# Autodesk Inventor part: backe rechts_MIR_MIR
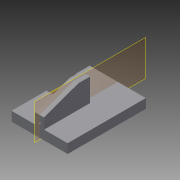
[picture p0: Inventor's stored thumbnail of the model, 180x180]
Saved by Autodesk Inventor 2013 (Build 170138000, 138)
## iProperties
Created: 2012-11
Part Number: backe rechts_MIR_MIR
Material: Allgemein
Document SubType Name: Modeling
Designer: otto
Density: 1 g/cm^3
Mass: 3948.56 g
Surface Area: 4189.4 cm^2
Volume: 3948.56 cm^3
d0: 1,000 oE
d1: 10,000 mm
d2: 10,000 mm
d3: 10,000 mm
d4: 60,000 mm
d5: 1,500 mm
d6: 0,00 grd
d7: 15,000 mm
d8: 0,00 grd
d9: 250,000 mm
d10: 49,000 mm
d11: 125,000 mm
d12: 0,00 grd
d13: 30,000 mm
d15: 200,000 mm
d16: 0,00 grd
d29: 5,000 mm
d31: 196,750 mm
d32: 0,00 grd
d33: 16,500 mm
d34: 0,00 grd
d35: 60,000 mm
d36: 0,00 grd
d37: 15,000 mm
d38: 0,00 grd
d0_1: 10,000 mm
Author: otto
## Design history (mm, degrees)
derived "backe rechts_MIR.ipt"
  sketch "Skizze2"
    geometry: L1 (62.842, 56.837)-(-16.083, -22.088) reference; L2 (62.842, 122.085)-(62.842, 56.837) reference; L3 (-3.226, -37.408)-(62.842, 28.66) reference; L4 (62.842, 28.66)-(62.842, -13.09) reference; L5 (62.842, -13.09)-(15.644, -60.289) reference; L6 (29.786, -74.431)-(62.842, -41.374) reference; L7 (62.842, -41.374)-(62.842, -94.979) reference; L8 (-14.414, -124.654)-(5.433, -104.806) reference; L9 (31.938, -124.654)-(-14.414, -124.654) reference; L10 (-7.843, -89.829)-(-42.668, -124.654) reference; L11 (-42.668, -124.654)-(-87.677, -124.654) reference; L12 (-87.677, -123.652)-(-29.098, -65.073) reference; L13 (103.52, -137.92)-(-134.48, -137.92) reference; L14 (103.52, -137.92)-(103.52, 384.83) reference; L15 (-134.48, 384.83)-(103.52, 384.83) reference; L16 (-134.48, -137.92)-(-134.48, 384.83) reference; L17 (-44.725, -52.895)-(-87.677, -95.847) reference; L18 (-87.677, -124.654)-(-87.677, -123.652) reference; L19 (-87.677, -95.847)-(-87.677, -45.538) reference; L20 (-125.48, -53.223)-(-125.48, 16.777) reference; L21 (-130.48, 16.777)-(-130.48, -53.223) reference; L22 (-130.48, -53.223)-(-125.48, -53.223) reference; L23 (99.52, 106.777)-(99.52, 176.777) reference; L24 (94.52, 176.777)-(94.52, 106.777) reference; L25 (94.52, 106.777)-(99.52, 106.777) reference; L26 (94.52, 176.777)-(99.52, 176.777) reference; L27 (-130.48, 16.777)-(-125.48, 16.777) reference; L28 (-135.48, 16.777)-(-130.48, 16.777) reference; L29 (99.52, 176.777)-(104.52, 176.777) reference; L30 (-135.48, 16.777)-(-135.48, 26.777) reference; L31 (-135.48, 26.777)-(-125.48, 26.777) reference; L32 (104.52, 176.777)-(104.52, 186.777) reference; L33 (104.52, 186.777)-(94.52, 186.777) reference; L34 (94.52, 186.777)-(34.52, 186.777) reference; L35 (34.52, 186.777)-(-125.48, 26.777) reference; 2 further points
  sketch "Skizze3"
    geometry: L1 (34.52, 186.777)-(-125.48, 26.777) reference; L2 (104.52, 186.777)-(34.52, 186.777) reference; L3 (104.52, 176.777)-(104.52, 186.777) reference; L4 (104.52, 176.777)-(104.52, 59.1) reference; L5 (104.52, 16.777)-(104.52, -143.223) reference; L6 (104.52, -143.223)-(-135.48, -143.223) reference; L7 (-135.48, -143.223)-(-135.48, 16.777) reference; L8 (-135.48, 26.777)-(-135.48, 16.777) reference; L9 (-125.48, 26.777)-(-135.48, 26.777) reference; A1 r 10.381 centre (114.837, 60.254) between (104.52, 59.1) and (115.363, 49.886) reference; A2 r 14.76 centre (116.112, 35.145) between (129.525, 28.983) and (115.363, 49.886) reference; A3 r 4.23 centre (125.681, 30.748) between (121.507, 31.429) and (129.525, 28.983) reference; A4 r 5.422 centre (116.156, 32.301) between (121.507, 31.429) and (112.095, 35.893) reference; A5 r 30.238 centre (134.744, 15.859) between (112.095, 35.893) and (104.52, 16.777) reference; 1 further point
  sketch "Skizze4"
    geometry: L1 (-305, 0)-(0, 0) reference; L2 (-147.5, -22.276)-(-147.5, 447.57) reference; L3 (-157.5, -22.276)-(-157.5, 447.57) reference; L4 (-128, 250)-(-177, 250) reference; L5 (-177, 250)-(-177, 0) reference; L6 (-177, 0)-(-128, 0) reference; L7 (-128, 0)-(-128, 250) reference; L8 (-152.5, 228.252)-(-152.5, 197.369) reference; 1 further point
  sketch "Skizze5"
    geometry: L1 (16.365, -23.986)-(187.376, 445.86) reference; L2 (45.244, -32.357)-(184.933, 351.435) reference; L3 (184.933, 351.435)-(190.607, -42.949) reference; L4 (190.607, -42.949)-(45.244, -32.357) reference; 1 further point
  sketch "Skizze6"
    geometry: L1 (10.563, -9.934)-(181.573, 459.912) reference; L2 (19.96, -13.354)-(190.97, 456.492) reference; L3 (140.058, 331.229)-(0.172, -53.104) reference; L4 (139.653, 330.118)-(134.966, 331.86) reference; L5 (16.052, -9.472)-(11.354, -7.762) reference; 1 further point
  sketch "Skizze11"
    geometry: L1 (169, -34)-(-69, -34) reference; L2 (-69, -34)-(-69, 34) reference; L3 (-69, 34)-(169, 34) reference; L4 (169, 34)-(169, -34) reference; L5 (169, 34)-(-69, 34) reference; L6 (-69, 34)-(-69, 0) reference; L7 (-69, 0)-(169, 0) reference; L8 (169, 0)-(169, 34) reference; 1 further point
  sketch "Skizze12"
    geometry: L1 (0, 0)-(0, 350) reference; L2 (-128, 0)-(0, 0) reference; L3 (-264, 350)-(-35, 350) reference; L4 (-264, 350)-(-264, 201) reference; L5 (-115, 350)-(-264, 201) reference; L6 (-128, 0)-(-128, 250) reference; L7 (-128, 250)-(-177, 250) reference; L8 (-177, 250)-(-177, 0) reference; L9 (-305, 0)-(-177, 0) reference; L10 (-305, 190)-(-305, 0) reference; L11 (-275, 190)-(-305, 190) reference; L12 (-115, 350)-(-275, 190) reference; L13 (0, 350)-(-115, 350) reference; 1 further point
  sketch "Skizze13"
    geometry: L1 (293, -44)-(293, 44) reference; L2 (293, 44)-(35, 44) reference; L3 (35, 44)-(35, -44) reference; L4 (305, 50.5)-(305, 0) reference; L5 (275, 50.5)-(305, 50.5) reference; L6 (264, 50.5)-(0, 50.5) reference; L7 (264, 50.5)-(275, 50.5) reference; L8 (0, 50.5)-(0, 0) reference; L9 (305, 0)-(293, 0) reference; L10 (35, 0)-(0, 0) reference; 1 further point
  sketch "Skizze14"
    geometry: L1 (293, 0)-(293, 44) reference; L2 (293, 44)-(35, 44) reference; L3 (35, 44)-(35, 0) reference; L4 (35, 0)-(0, 0) reference; L5 (0, 0)-(0, 50.5) reference; L6 (0, 50.5)-(305, 50.5) reference; L7 (305, 50.5)-(305, 0) reference; L8 (305, 0)-(293, 0) reference; L9 (283, -34)-(283, 34) reference; L10 (283, 34)-(45, 34) reference; L11 (45, 34)-(45, -34) reference; L12 (293, 0)-(283, 0) reference; L13 (45, 0)-(35, 0) reference; 1 further point
  workplane "Arbeitsebene1"
  workplane "Arbeitsebene2"
feature "Volumenkörper1::backe rechts_MIR.ipt"
tag "Bezeichnung1"
node "Volumenkörper1"
other parameters: "d0_1" = 10, "d9" = 250, "d10" = 49, "d11" = 125, "d12" = 0, "d13" = 30, "d15" = 200, "d16" = 0, "d29" = 5, "d31" = 196.75, "d32" = 0, "d33" = 16.5, "d34" = 0, "d35" = 60, "d36" = 0, "d37" = 15, "d38" = 0, "d1" = 10, "d2" = 10, "d3" = 10, "d4" = 60, "d5" = 1.5, "d6" = 0, "d7" = 15, "d8" = 0
